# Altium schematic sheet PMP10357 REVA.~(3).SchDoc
size 431 x 279 mm; Date: Not shown in title block; ApprovedBy: Not shown in title block; CheckedBy: Not shown in title block; Author: Not shown in title block; CompanyName: Not shown in title block; Engineer: Not shown in title block; Organization: Not shown in title block; Address1: Not shown in title block; Address2: Not shown in title block; Address3: Not shown in title block; Address4: Not shown in title block; DocumentNumber: 1; Revision: Use project parameter SCH_Rev; SheetNumber: 1; SheetTotal: 1; PageSetup: Record=PageOptions|CenterHorizontal=True|CenterVertical=True|PrintScale=1.00|XCorrection=1.00|YCorrection=1.00|PrintKind=0|BorderSize=5000000|LeftOffset=0|BottomOffset=0|Orientation=2|PaperLength=1000|PaperWidth=1000|Scale=100|PaperSource=15|PrintQuality=600|MediaType=1|DitherType=10|PaperKind=Letter|PrintScaleMode=1
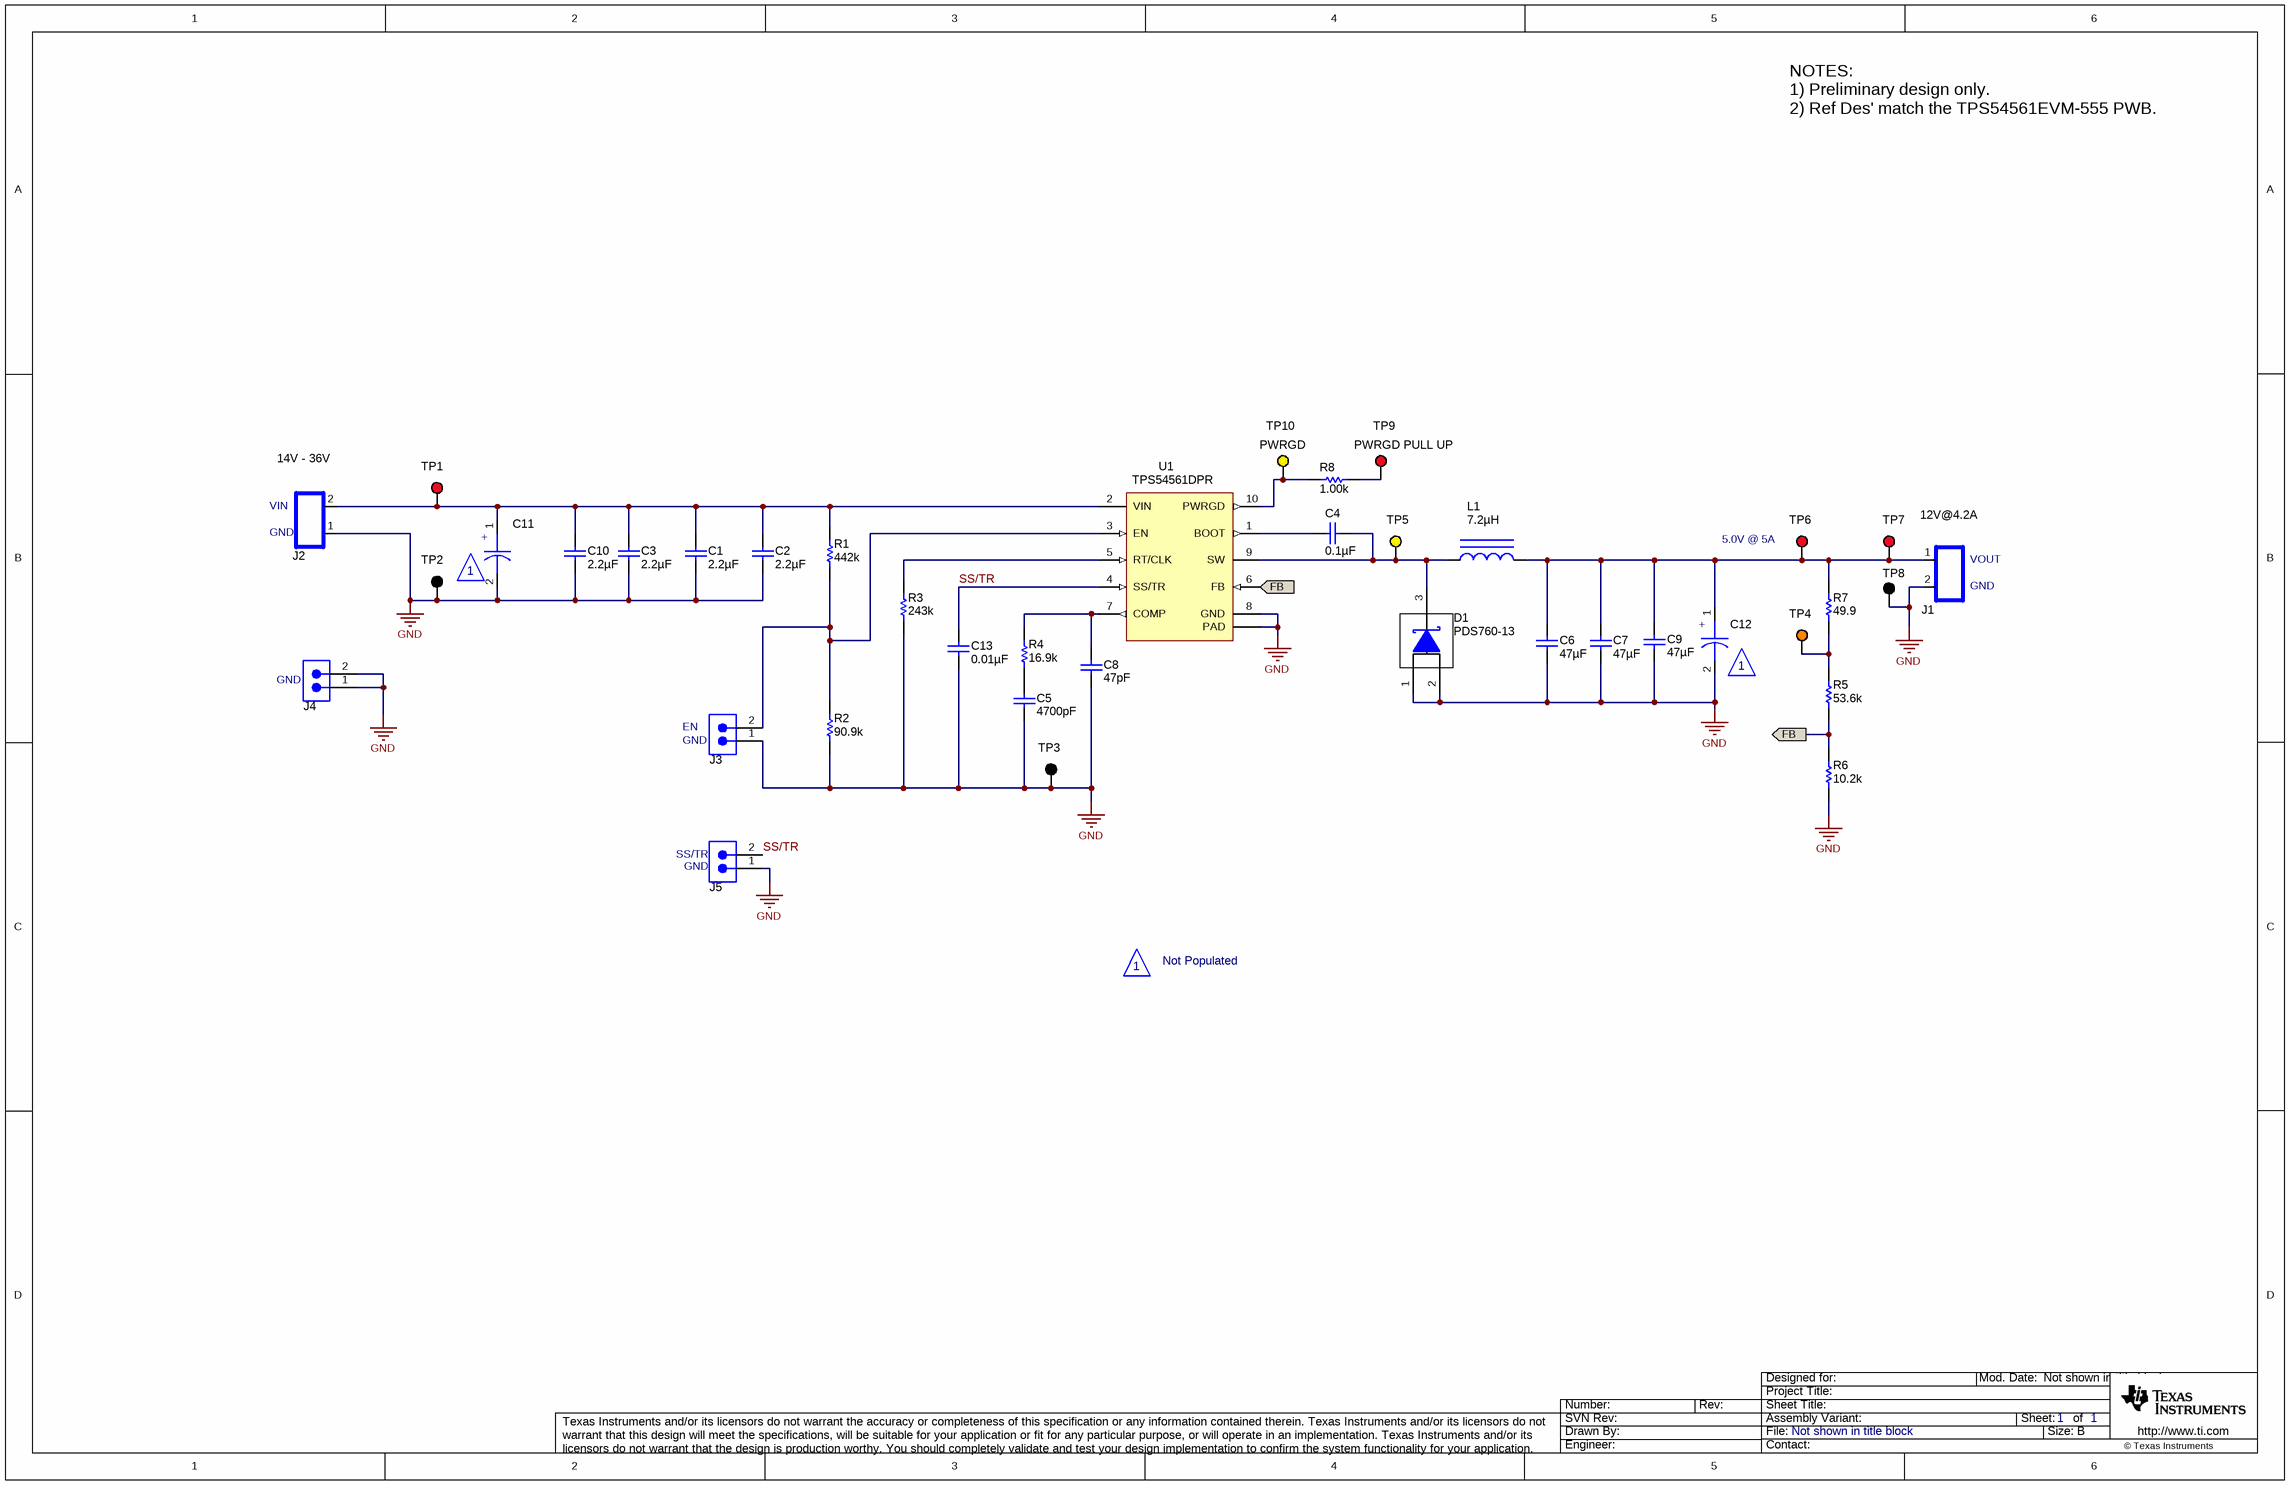
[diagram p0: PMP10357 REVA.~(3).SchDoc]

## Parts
C1  ValueDisplayed: 2.2µF  [1210]  (hidden comment: GRM32ER72A225KA35L)
C2  ValueDisplayed: 2.2µF  [1210]  (hidden comment: GRM32ER72A225KA35L)
C3  ValueDisplayed: 2.2µF  [1210]  (hidden comment: GRM32ER72A225KA35L)
C4  ValueDisplayed: 0.1µF  [0603]  (hidden comment: C0603C104K8RACTU)
C5  ValueDisplayed: 4700pF  [0603]  (hidden comment: C0603C472J5RACTU)
C6  ValueDisplayed: 47µF  [1210]  (hidden comment: GRM32ER61C476ME15L)
C7  ValueDisplayed: 47µF  [1210]  (hidden comment: GRM32ER61C476ME15L)
C8  ValueDisplayed: 47pF  [0603]  (hidden comment: 06035A470JAT2A)
C9  ValueDisplayed: 47µF  [1210]  (hidden comment: GRM32ER61C476ME15L)
C10  ValueDisplayed: 2.2µF  [1210]  (hidden comment: GRM32ER72A225KA35L)
C11  Engineering Only  [C_SM-1210/E_TH-F]  (value not drawn)
C12  Engineering Only  [C_SM-1210/E_TH-F]  (value not drawn)
C13  ValueDisplayed: 0.01µF  [0603]  (hidden comment: C0603C103K5RACTU)
D1  PDS760-13  [PowerDI5]
J1  TBLK_15A_2X5.1MM  [TB_2X5.1MM]  (value not drawn)
J2  TBLK_15A_2X5.1MM  [TB_2X5.1MM]  (value not drawn)
J3  TSW-102-07-G-S  [TSW-102-07-G-S]  (value not drawn)
J4  TSW-102-07-G-S  [TSW-102-07-G-S]  (value not drawn)
J5  TSW-102-07-G-S  [TSW-102-07-G-S]  (value not drawn)
L1  ValueDisplayed: 7.2µH  [WE-PDF_1064]  (hidden comment: 7447798720)
R1  value 442k  [0603]  (hidden comment: CRCW0603442KFKEA)
R2  value 90.9k  [0603]  (hidden comment: CRCW060390K9FKEA)
R3  value 243k  [0603]  (hidden comment: CRCW0603243KFKEA)
R4  value 16.9k  [0603]  (hidden comment: CRCW060316K9FKEA)
R5  value 53.6k  [0603]  (hidden comment: CRCW060353K6FKEA)
R6  value 10.2k  [0603]  (hidden comment: CRCW060310K2FKEA)
R7  value 49.9  [0603]  (hidden comment: CRCW060349R9FKEA)
R8  value 1.00k  [0603]  (hidden comment: CRCW06031K00FKEA)
TP1  5010  [Keystone5010]  (value not drawn)
TP2  5011  [Keystone5011]  (value not drawn)
TP3  5011  [Keystone5011]  (value not drawn)
TP4  5013  [Keystone5013]  (value not drawn)
TP5  5014  [Keystone5014]  (value not drawn)
TP6  5010  [Keystone5010]  (value not drawn)
TP7  5010  [Keystone5010]  (value not drawn)
TP8  5011  [Keystone5011]  (value not drawn)
TP9  5010  [Keystone5010]  (value not drawn)
TP10  5014  [Keystone5014]  (value not drawn)
U1  TPS54561DPR  [DPR0010A]

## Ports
FB (in), FB (out)

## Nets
GND: C1.2 C2.2 C3.2 C5.2 C6.2 C7.2 C8.2 C9.2 C10.2 C11.2 C12.2 C13.2 D1.1(A) D1.2(A) J1.2 J2.1 J3.1 J4.1 J4.2 J5.1 R2.1 R3.1 R6.1 TP2.1 TP3.1 TP8.1 U1.8(GND) U1.11(PAD)
FB: R5.1 R6.2 U1.6(FB) ; port FB
SS/TR: C13.1 J5.2 U1.4(SS/TR)
NetC1_1: C1.1 C2.1 C3.1 C10.1 C11.1 J2.2 R1.2 TP1.1 U1.2(VIN)
NetC4_1: C4.1 D1.3(K) L1.1 TP5.1 U1.9(SW)
NetC4_2: C4.2 U1.1(BOOT)
NetC5_1: C5.1 R4.1
NetC6_1: C6.1 C7.1 C9.1 C12.1 J1.1 L1.2 R7.2 TP6.1 TP7.1
NetC8_1: C8.1 R4.2 U1.7(COMP)
NetJ3_2: J3.2 R1.1 R2.2 U1.3(EN)
NetR3_2: R3.2 U1.5(RT/CLK)
NetR5_2: R5.2 R7.1 TP4.1
NetR8_1: R8.1 TP10.1 U1.10(PWRGD)
NetR8_2: R8.2 TP9.1

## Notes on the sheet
- NOTES:
  1) Preliminary design only.
  2) Ref Des' match the TPS54561EVM-555 PWB.
- (near J2) 14V - 36V
- (near TP10) PWRGD
- (near TP9) PWRGD PULL UP
- (near J2) VIN
- (near J2) GND
- (near TP6) 5.0V @ 5A
- 12V@4.2A
- (near J1) VOUT
- 1
- (near J1) GND
- (near J4) GND
- (near C12) 1
- (near J3) EN
- (near J3) GND
- (near J5) SS/TR
- (near J5) GND
- Not Populated

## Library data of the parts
C1-C3 C10 = GRM32ER72A225KA35L: CAP, CERM, 2.2uF, 100V, +/-10%, X7R, 1210; Manufacturer: MuRata; Polarized: N; CompType: Capacitor; U/M: EA; Cap_F: 0.0000022; Tolerance_%: 10; ESR_Ohm: 0.007; Value1: 0.007 ohm; VDC_V: 100; IRMS_A: 4.4; TaMin_C: -55; TaMax_C: 125
C4 = C0603C104K8RACTU: CAP, CERM, 0.1uF, 10V, +/-10%, X7R, 0603; Manufacturer: Kemet; Polarized: N; CompType: Capacitor; U/M: EA; Cap_F: 0.0000001; Tolerance_%: 10; TaMin_C: -55; TaMax_C: 125
C5 = C0603C472J5RACTU: CAP, CERM, 4700pF, 50V, +/-5%, X7R, 0603; Manufacturer: Kemet; Polarized: N; CompType: Capacitor; U/M: EA; Cap_F: 0.0000000047; Tolerance_%: 5; VDC_V: 50; TaMin_C: -55; TaMax_C: 125
C6 C7 C9 = GRM32ER61C476ME15L: CAP, CERM, 47uF, 16V, +/-20%, X5R, 1210; Manufacturer: MuRata; Polarized: N; CompType: Capacitor; U/M: EA; Cap_F: 0.000047; Tolerance_%: 20; ESR_Ohm: 0.002; Value1: 0.002 ohm; VDC_V: 16; TaMin_C: -55; TaMax_C: 85
C8 = 06035A470JAT2A: CAP, CERM, 47pF, 50V, +/-5%, C0G/NP0, 0603; Manufacturer: AVX; Polarized: N; CompType: Capacitor; U/M: EA; Cap_F: 0.000000000047; Tolerance_%: 5; ESR_Ohm: 0.174; Value1: 0.174 ohm; VDC_V: 50; TaMin_C: -55; TaMax_C: 125
C11 C12 = C-MULTI_1210-F: Capacitor, Aluminum, vvV, 20%; Manufacturer: {MFR}; Alternate Manufacturer: Any; Alternate PartNumber: Equivalent; Area: 168100; Value: {Value}
C13 = C0603C103K5RACTU: CAP, CERM, 0.01uF, 50V, +/-10%, X7R, 0603; Manufacturer: Kemet; Polarized: N; CompType: Capacitor; U/M: EA; Cap_F: 0.00000001; Tolerance_%: 10; Value1: Unknown; VDC_V: 50; TaMin_C: -55; TaMax_C: 125
D1 = PDS560-13: Diode, Schottky, 60V, 7A, PowerDI5; Manufacturer: Diodes Inc.; U/M: EA; Vf_V: 0.56; Io_A: 7; Vr_V: 60; Value2: 0.56V; TJmax_C: 150
J1 J2 = TBLK_15A_2X5.1MM: Terminal Block, 2-pin, 15-A, 5.1mm; Manufacturer: OST; PartNumber: ED120/2DS; Alternate Manufacturer: Any; Alternate PartNumber: Equivalent; area: 141600; Value: ED120/2DS
J3-J5 = TSW-102-07-G-S: Header, TH, 100mil, 2x1, Gold plated, 230 mil above insulator; Manufacturer: Samtec, Inc.; U/M: EA
L1 = 7447798720: Inductor, Shielded, Metal Composite, 7.2uH, 6A, 0.0113 ohm, SMD; Manufacturer: Wurth Elektronik eiSos; Ind_H: 7.2E-6; Imax_A: 6; Irms: 7.9A @ 40C rise; Isat: 6A @ 10% inductance drop; DCR_ohm: 0.0113; U/M: EA
R1 = CRCW0603442KFKEA: RES, 442k ohm, 1%, 0.1W, 0603; Manufacturer: Vishay-Dale; Alternate Manufacturer: Any; Alternate PartNumber: Equivalent; CompType: Resistor; Res_ohm: 442000; Tolerance_%: 1; Power_W: 0.1; VDC_V: 75; TempCo: 100 ppm/C; EIA_Code: E96; U/M: EA
R2 = CRCW060390K9FKEA: RES, 90.9k ohm, 1%, 0.1W, 0603; Manufacturer: Vishay-Dale; Alternate Manufacturer: Any; Alternate PartNumber: Equivalent; CompType: Resistor; Res_ohm: 90900; Value_Code: 90k9; Tolerance_%: 1; Power_W: 0.1; VDC_V: 75; TempCo: 100 ppm/C; EIA_Code: E96; U/M: EA
R3 = CRCW0603243KFKEA: RES, 243k ohm, 1%, 0.1W, 0603; Manufacturer: Vishay-Dale; Alternate Manufacturer: Any; Alternate PartNumber: Equivalent; CompType: Resistor; Res_ohm: 243000; Tolerance_%: 1; Power_W: 0.1; VDC_V: 75; TempCo: 100 ppm/C; EIA_Code: E96; U/M: EA
R4 = CRCW060316K9FKEA: RES, 16.9k ohm, 1%, 0.1W, 0603; Manufacturer: Vishay-Dale; Alternate Manufacturer: Any; Alternate PartNumber: Equivalent; CompType: Resistor; Res_ohm: 16900; Value_Code: 16k9; Tolerance_%: 1; Power_W: 0.1; VDC_V: 75; TempCo: 100 ppm/C; EIA_Code: E96; U/M: EA
R5 = CRCW060353K6FKEA: RES, 53.6k ohm, 1%, 0.1W, 0603; Manufacturer: Vishay-Dale; Alternate Manufacturer: Any; Alternate PartNumber: Equivalent; CompType: Resistor; Res_ohm: 53600; Value_Code: 53k6; Tolerance_%: 1; Power_W: 0.1; VDC_V: 75; TempCo: 100 ppm/C; EIA_Code: E96; U/M: EA
R6 = CRCW060310K2FKEA: RES, 10.2k ohm, 1%, 0.1W, 0603; Manufacturer: Vishay-Dale; Alternate Manufacturer: Any; Alternate PartNumber: Equivalent; CompType: Resistor; Res_ohm: 10200; Value_Code: 10k2; Tolerance_%: 1; Power_W: 0.1; VDC_V: 75; TempCo: 100 ppm/C; EIA_Code: E96; U/M: EA
R7 = CRCW060349R9FKEA: RES, 49.9 ohm, 1%, 0.1W, 0603; Manufacturer: Vishay-Dale; Alternate Manufacturer: Any; Alternate PartNumber: Equivalent; CompType: Resistor; Value_Code: 49R9; Tolerance_%: 1; Power_W: 0.1; VDC_V: 75; TempCo: 100 ppm/C; EIA_Code: E96; U/M: EA
R8 = CRCW06031K00FKEA: RES, 1.00k ohm, 1%, 0.1W, 0603; Manufacturer: Vishay-Dale; CompType: Resistor; Res_ohm: 1000; Value_Code: 1k00; Tolerance_%: 1; Power_W: 0.1; VDC_V: 75; TempCo: 100 ppm/C; EIA_Code: E96; U/M: EA
TP1 TP6 TP7 TP9 = 5010: Test Point, TH, Multipurpose, Red; Manufacturer: Keystone; CompType: Test Point Loop; U/M: EA
TP2 TP3 TP8 = 5011: Test Point, TH, Multipurpose, Black; Manufacturer: Keystone; CompType: Test Point Loop; U/M: EA
TP4 = 5013: Test Point, TH, Multipurpose, Orange; Manufacturer: Keystone; CompType: Test Point Loop; U/M: EA
TP5 TP10 = 5014: Test Point, TH Multipurpose, Yellow; Manufacturer: Keystone; CompType: Test Point Loop; U/M: EA
U1 = TPS54561DPR: 60 V Input, 5 A, Step Down DC-DC Converter with Soft-Start and Eco-mode, DPR0010A; Alternate Manufacturer: None; Manufacturer: Texas Instruments; SymbolCreator: a0411947; CompType: IC; U/M: EA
